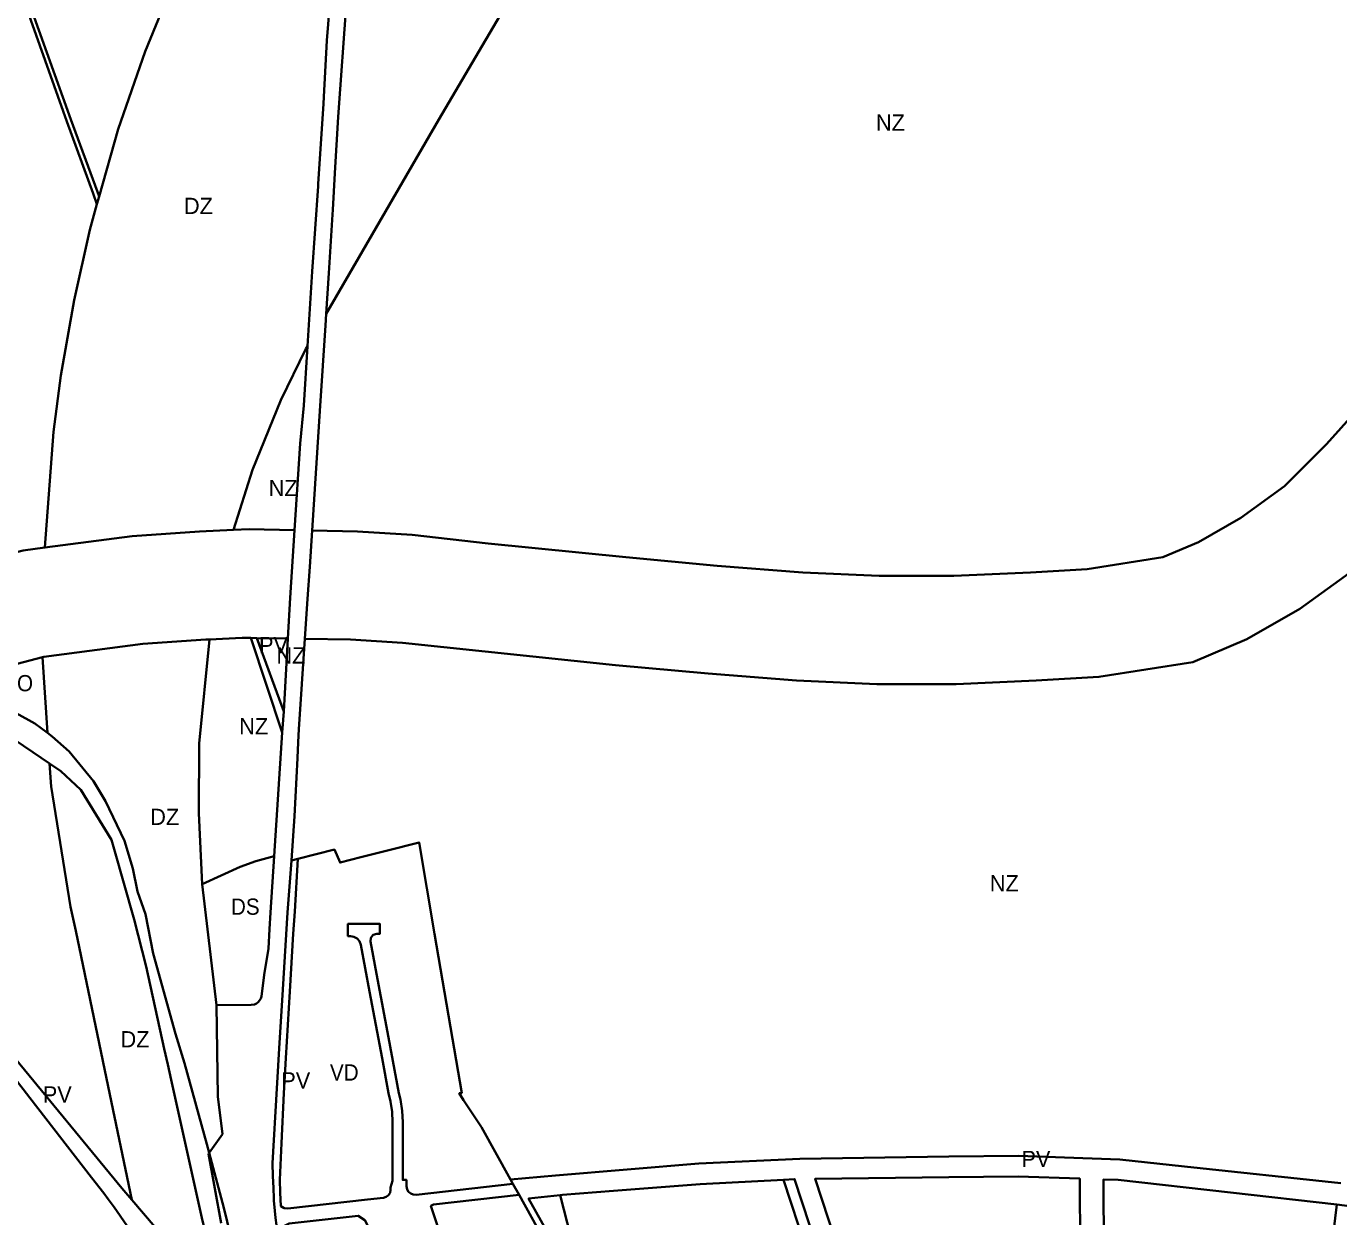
# Model space of a CAD drawing. Extents: x -650451 to -642268, y -1075216 to -1066610.
# Drawn here: x -648056 to -646844, y -1069586 to -1068487 of the extents above; entities that cross this region are included whole.
import ezdxf

# ---------------------------------------------------------------- set-up
doc = ezdxf.new("R2010")
doc.units = 0
doc.header["$LTSCALE"] = 6
doc.layers.add('1', color=7, linetype='Continuous', lineweight=35)
doc.layers.add('2', color=7, linetype='Continuous')
doc.layers.add('3', color=7, linetype='Continuous')

msp = doc.modelspace()

# ---------------------------------------------------------------- linework, layer by layer
at = {"layer": '1'}
for p, q in [((-647988.607, -1068644.072), (-647990.625, -1068651.217)), ((-647848.615, -1069051.679), (-647842.888, -1069051.774)), ((-647814.401, -1069052.246), (-647842.888, -1069051.774)), ((-647818.08, -1069119.56), (-647842.888, -1069051.774)), ((-648036.291, -1069139.458), (-648040.705, -1069069.547)), ((-647805.14, -1069255.7), (-647811.084, -1069257.214)), ((-647880.326, -1069390.832), (-647893.553, -1069279.017)), ((-647608.81, -1069551.868), (-647606.53, -1069555.98)), ((-647356.899, -1069552.034), (-647266.581, -1069827.042))]:
    msp.add_line(p, q, dxfattribs=at)
for points in [[(-647778.95, -1068752.433), (-647675.054, -1068572.919), (-647419.74, -1068138.917)], [(-647812.6, -1068183.94), (-647823.67, -1068190.63), (-647913.43, -1068244.8), (-647923.95, -1068250.62), (-647932.13, -1068255.14), (-647994.99, -1068289.93), (-648077.22, -1068335.42), (-648096.72, -1068347.09), (-648093.84, -1068353.13), (-648084.05, -1068373.6), (-648051.48, -1068469.81), (-648014.58, -1068572.99), (-647990.12, -1068639.62), (-647988.607, -1068644.072)], [(-647778.95, -1068752.433), (-647776.5, -1068714.8), (-647773.4, -1068665.71), (-647773.08, -1068660.57), (-647772.85, -1068656.41), (-647770.94, -1068622.47), (-647768.02, -1068570.36), (-647760.22, -1068463.96), (-647757.41, -1068419.98), (-647754.99, -1068378.21), (-647756.09, -1068337.61), (-647758.45, -1068317.66), (-647765.22, -1068287.94), (-647791.055, -1068200.507)], [(-647801.797, -1068219.34), (-647843.6, -1068292.629), (-647868.214, -1068337.803), (-647914.339, -1068432.512), (-647946.187, -1068510.254), (-647971.074, -1068581.98), (-647988.607, -1068644.072)], [(-647796.173, -1068782.191), (-647791.77, -1068713.23), (-647786.47, -1068634.37), (-647786.32, -1068632.19), (-647781.85, -1068562.97), (-647781.55, -1068558.38), (-647781.13, -1068551.88), (-647778.24, -1068499.95), (-647775.82, -1068469.74), (-647775.52, -1068464.97), (-647771.74, -1068404.5), (-647771.47, -1068400.07), (-647770.12, -1068377.5), (-647769.92, -1068352.1), (-647770.81, -1068340.29), (-647771.05, -1068337.01), (-647774.94, -1068311.47), (-647779.55, -1068292.23), (-647780.07, -1068290.53), (-647801.797, -1068219.34)], [(-648541.25, -1068592.3), (-648536.92, -1068589.8), (-648494.56, -1068565.28), (-648457.28, -1068545.66), (-648400.38, -1068515.71), (-648295.53, -1068457.31), (-648120.88, -1068361.55), (-648100.65, -1068349.44), (-648095.04, -1068361.96), (-648088.12, -1068377.42), (-648055.06, -1068471.54), (-648018.36, -1068574.68), (-647994.1, -1068641.2), (-647990.625, -1068651.217)], [(-647990.625, -1068651.217), (-647997.27, -1068674.747), (-648011.775, -1068739.718), (-648023.914, -1068809.332), (-648030.73, -1068861.213), (-648038.596, -1068968.281)], [(-646562.49, -1068790.69), (-646575.28, -1068775.04), (-646583.98, -1068766.42), (-646592.53, -1068758.66), (-646601.86, -1068751.01), (-646613.44, -1068743.65), (-646617.991, -1068741.503), (-646673.05, -1068812.491), (-646741.85, -1068895.719), (-646782.784, -1068941.581), (-646829.104, -1068987.917), (-646880.163, -1069024.903), (-646929.186, -1069052.925), (-646978.92, -1069073.93), (-647065.688, -1069087.73), (-647123.648, -1069091.043), (-647197.498, -1069094.255), (-647270.522, -1069094.255), (-647344.902, -1069091.02), (-647426.417, -1069084.624), (-647511.94, -1069076.703), (-647708.401, -1069056.275), (-647756.441, -1069053.207), (-647798.631, -1069052.508)], [(-647778.95, -1068752.433), (-647779.65, -1068763.19), (-647784.48, -1068837.2), (-647792.01, -1068952.442)], [(-647864.531, -1068951.823), (-647846.989, -1068896.545), (-647820.883, -1068832.117), (-647797.632, -1068784.713), (-647796.173, -1068782.191)], [(-647808.28, -1068952.066), (-647803.08, -1068872.18), (-647799.68, -1068837.13), (-647796.173, -1068782.191)], [(-646817.718, -1068830.545), (-646855.506, -1068872.883), (-646894.206, -1068911.595), (-646934.465, -1068940.759), (-646973.61, -1068963.135), (-647006.63, -1068977.08), (-647076.422, -1068988.18), (-647128.674, -1068991.167), (-647199.672, -1068994.255), (-647268.348, -1068994.255), (-647338.816, -1068991.19), (-647417.895, -1068984.986), (-647502.412, -1068977.157), (-647629.424, -1068964.608), (-647699.561, -1068956.635), (-647749.978, -1068953.416), (-647792.01, -1068952.442)], [(-648038.596, -1068968.281), (-647958.168, -1068957.73), (-647895.901, -1068953.392), (-647864.531, -1068951.823)], [(-647808.28, -1068952.066), (-647850.043, -1068951.098), (-647864.531, -1068951.823)], [(-647814.401, -1069052.246), (-647812.34, -1069014.54), (-647808.28, -1068952.066)], [(-647792.01, -1068952.442), (-647794.21, -1068986.12), (-647796.13, -1069015.57), (-647798.631, -1069052.508)], [(-648038.596, -1068968.281), (-648038.596, -1068968.284), (-648038.596, -1068968.284), (-648038.746, -1068968.301), (-648058.764, -1068970.927), (-648156.739, -1068996.273), (-648347.522, -1069078.405)], [(-648040.705, -1069069.547), (-648039.666, -1069069.279), (-647948.18, -1069057.276), (-647889.927, -1069053.218), (-647886.615, -1069053.052)], [(-647886.615, -1069053.052), (-647896.362, -1069149.171), (-647896.67, -1069213.573), (-647893.553, -1069279.017)], [(-647886.615, -1069053.052), (-647856.541, -1069051.548), (-647848.615, -1069051.679)], [(-647848.615, -1069051.679), (-647819.71, -1069139.14), (-647826.928, -1069253.199)], [(-647819.71, -1069139.14), (-647818.08, -1069119.56), (-647814.401, -1069052.246)], [(-647798.631, -1069052.508), (-647804.28, -1069135.95), (-647804.49, -1069141.9), (-647805.14, -1069155.17), (-647805.51, -1069162.87), (-647808.12, -1069216.3), (-647811.084, -1069257.214)], [(-648040.705, -1069069.547), (-648124.327, -1069091.181), (-648144.866, -1069099.987)], [(-648036.291, -1069139.458), (-648048.06, -1069130.81), (-648065.16, -1069121.12), (-648100.37, -1069107.1), (-648139.27, -1069100.05), (-648144.866, -1069099.987)], [(-648280.1, -1069166.97), (-648275.19, -1069162.87), (-648270.92, -1069159.99), (-648248.14, -1069144.65), (-648209.89, -1069130.36), (-648207.77, -1069129.95), (-648171.14, -1069122.83), (-648141.92, -1069121.66), (-648073.66, -1069140.86), (-648034.421, -1069167.61)], [(-647887.087, -1069527.229), (-647889.22, -1069519.32), (-647909.67, -1069444.46), (-647918.08, -1069417.43), (-647938.77, -1069343.17), (-647945.63, -1069306.95), (-647953.01, -1069285.73), (-647957.56, -1069264.74), (-647965.06, -1069238.95), (-647982.58, -1069202.33), (-647993.8, -1069184.11), (-648016.36, -1069156.54), (-648031.92, -1069142.67), (-648036.291, -1069139.458)], [(-648280.1, -1069166.97), (-648203.01, -1069264.73), (-648127.77, -1069361.38), (-648068.71, -1069436.57), (-647967.53, -1069559.94), (-647958.34, -1069570.698)], [(-647958.34, -1069570.698), (-647980.331, -1069465.915), (-648010.092, -1069322.087), (-648015, -1069300), (-648033, -1069189), (-648034.421, -1069167.61)], [(-647843.443, -1069768.293), (-647852.78, -1069745.71), (-647859.722, -1069722.428), (-647872.87, -1069673.56), (-647893.75, -1069587.08), (-647922.04, -1069459.71), (-647925.16, -1069445.68), (-647928.41, -1069431.03), (-647945.28, -1069355.1), (-647956.27, -1069311.58), (-647974.81, -1069246.86), (-647977.29, -1069238.21), (-648005.47, -1069192.09), (-648024.02, -1069174.7), (-648034.421, -1069167.61)], [(-648290.39, -1069177.69), (-648280.46, -1069187.61), (-648147.81, -1069355.26), (-648143.81, -1069359.39), (-648116.93, -1069393.25), (-648052.62, -1069476.32), (-647995.61, -1069549.95), (-647984.36, -1069564.49), (-647980.21, -1069569.97), (-647974.74, -1069577.39), (-647962.93, -1069594.39), (-647942.48, -1069623.82), (-647922.32, -1069649.56), (-647909.25, -1069673.35)], [(-647805.14, -1069255.7), (-647771.45, -1069247.12), (-647766.21, -1069259.15), (-647746.96, -1069254.25), (-647723.69, -1069248.33), (-647693.15, -1069240.55), (-647678.84, -1069324.94), (-647664.224, -1069411.034), (-647653.86, -1069472.12), (-647656.18, -1069472.12), (-647652.23, -1069478.65), (-647635.69, -1069503.4), (-647608.81, -1069551.868)], [(-647826.928, -1069253.199), (-647843.873, -1069257.994), (-647858.37, -1069263.03), (-647893.553, -1069279.017)], [(-647880.326, -1069390.832), (-647848.24, -1069390.65), (-647845.25, -1069390.07), (-647843.41, -1069389.23), (-647841.81, -1069387.99), (-647840.42, -1069386.51), (-647839.4, -1069384.73), (-647838.79, -1069382.86), (-647836.2, -1069362.68), (-647832.29, -1069338.58), (-647831.19, -1069320.69), (-647830.23, -1069305.38), (-647826.928, -1069253.199)], [(-647774.11, -1069689.64), (-647790.88, -1069695.49), (-647793.77, -1069690.4), (-647800.98, -1069677.69), (-647805.51, -1069669.7), (-647816.39, -1069647.74), (-647818.42, -1069632.36), (-647820.07, -1069619.78), (-647823.88, -1069600.72), (-647825.89, -1069587.19), (-647827.1, -1069574.34), (-647827.22, -1069571.45), (-647827.31, -1069569.36), (-647827.71, -1069559.64), (-647828.17, -1069548.8), (-647828.68, -1069536.6), (-647824.5, -1069467.9), (-647821.93, -1069425.59), (-647819.51, -1069386.41), (-647814.57, -1069305.32), (-647811.084, -1069257.214)], [(-647606.53, -1069555.98), (-647696.02, -1069565.92), (-647698.57, -1069565.78), (-647700.95, -1069564.85), (-647702.91, -1069563.21), (-647704.25, -1069561.03), (-647704.84, -1069558.02), (-647704.84, -1069552.17), (-647708.22, -1069552.17), (-647708.22, -1069498.99), (-647708.76, -1069488.38), (-647710.39, -1069477.9), (-647711.77, -1069472.12), (-647721.4, -1069420.72), (-647731.52, -1069366.76), (-647738.02, -1069332.04), (-647737.66, -1069328.61), (-647735.46, -1069325.95), (-647732.16, -1069324.94), (-647729.31, -1069324.94), (-647729.31, -1069315.76), (-647758.86, -1069315.76), (-647758.86, -1069327.02), (-647756.65, -1069327.02), (-647753.34, -1069327.6), (-647750.43, -1069329.27), (-647748.26, -1069331.82), (-647747.08, -1069334.97), (-647738.95, -1069378.31), (-647727.42, -1069439.81), (-647721.36, -1069472.12), (-647721.57, -1069472.12), (-647719.63, -1069479.82), (-647718.14, -1069489.35), (-647717.65, -1069498.99), (-647717.65, -1069553.07), (-647719.45, -1069559.07), (-647719.45, -1069561.35), (-647719.94, -1069564), (-647721.35, -1069566.32), (-647723.49, -1069567.97), (-647726.08, -1069568.75), (-647740.9, -1069570.4), (-647814.52, -1069578.58), (-647817.86, -1069578.21), (-647820.72, -1069576.46), (-647821.44, -1069563.8), (-647821.65, -1069552.11), (-647820.28, -1069518.33), (-647818.17, -1069472.12), (-647816.33, -1069439.81), (-647812.64, -1069378.31), (-647809.46, -1069324.94), (-647807.97, -1069304.43), (-647805.14, -1069255.7)], [(-647887.087, -1069527.229), (-647874.75, -1069509.84), (-647878.93, -1069475.09), (-647880.326, -1069390.832)], [(-647887.087, -1069527.229), (-647887.649, -1069528.021), (-647876.056, -1069592.232)], [(-647852.44, -1069664.03), (-647873.43, -1069577.87), (-647887.087, -1069527.229)], [(-647608.81, -1069551.868), (-647567.252, -1069548.083), (-647434.969, -1069537.141), (-647341.697, -1069532.602), (-647204.293, -1069530.647), (-647140.008, -1069530.068), (-647046.325, -1069533.275), (-646986.633, -1069539.757), (-646842.441, -1069555.283)], [(-647256.061, -1069697.32), (-647277.71, -1069703.421), (-647327.682, -1069551.263), (-647204.208, -1069549.647), (-647140.247, -1069549.071), (-647083.356, -1069551.018), (-647082.761, -1069681.399), (-647113.255, -1069679.966), (-647139.649, -1069679.961), (-647203.374, -1069684.716), (-647219.628, -1069686.746), (-647251.002, -1069695.852), (-647251.13, -1069695.888)], [(-647606.53, -1069555.98), (-647600.891, -1069566.14), (-647573.15, -1069616.16)], [(-647356.899, -1069552.034), (-647433.779, -1069556.106), (-647513.66, -1069562.249), (-647560.836, -1069566.036), (-647563.104, -1069566.28)], [(-647256.034, -1069827.107), (-647346.554, -1069551.486), (-647356.899, -1069552.034)], [(-646862.955, -1069713.633), (-647060.7, -1069683.894), (-647061.304, -1069551.773), (-647047.702, -1069552.239), (-646944.167, -1069563.743), (-646846, -1069575)], [(-647875.82, -1069701.85), (-647883.51, -1069682.71), (-647906.16, -1069641.48), (-647925.99, -1069608.57), (-647958.34, -1069570.698)], [(-647600.891, -1069566.14), (-647679.81, -1069574.91), (-647682.22, -1069576.19), (-647675.26, -1069597.24), (-647718.71, -1069611.6), (-647727.55, -1069614.52), (-647729.31, -1069615.1), (-647743.25, -1069589.24), (-647749.4, -1069585.37), (-647813.02, -1069592.44), (-647818.74, -1069595.32), (-647815.08, -1069616.01), (-647809.52, -1069641.61), (-647806.38, -1069650.88), (-647802.83, -1069659.58), (-647800.97, -1069663.54), (-647793.91, -1069678.36), (-647784.61, -1069683.92), (-647779.26, -1069684.27), (-647659.57, -1069644.72), (-647573.15, -1069616.16)], [(-647563.104, -1069566.28), (-647592.199, -1069569.411), (-647555.266, -1069635.207), (-647530.471, -1069671.013), (-647440.459, -1069836.56)], [(-647563.104, -1069566.28), (-647546.777, -1069629.901), (-647521.943, -1069665.763), (-647428.993, -1069836.714)], [(-646755.269, -1069587.04), (-646846, -1069575), (-646862.955, -1069713.633)]]:
    msp.add_lwpolyline(points, dxfattribs=at)

# ---------------------------------------------------------------- texts
at = {"layer": '2'}
for s, p in [('NZ', (-647271.461, -1068583.283)), ('NZ', (-647832.089, -1068920.764)), ('PV', (-647840.968, -1069065.795)), ('NZ', (-647824.885, -1069075.376)), ('NZ', (-647859.243, -1069140.767)), ('NZ', (-647166.355, -1069285.772)), ('PV', (-647820.414, -1069467.809))]:
    msp.add_text(s, height=15, dxfattribs=at).set_placement(p)
at = {"layer": '2', "width": 0.95}
msp.add_text('VD', height=15, dxfattribs=at).set_placement((-647775.487, -1069460.491))
at = {"layer": '3'}
for s, p in [('DZ', (-647910.265, -1068660.202)), ('DZ', (-647941.405, -1069224.432)), ('DZ', (-647968.838, -1069429.808)), ('PV', (-648040.586, -1069480.779)), ('PV', (-647137.157, -1069540.359))]:
    msp.add_text(s, height=15, dxfattribs=at).set_placement(p)
at = {"layer": '3', "width": 0.95}
for s, p in [('ZO', (-648076.028, -1069100.974)), ('DS', (-647866.885, -1069307.358))]:
    msp.add_text(s, height=15, dxfattribs=at).set_placement(p)

doc.saveas('drawing.dxf')
